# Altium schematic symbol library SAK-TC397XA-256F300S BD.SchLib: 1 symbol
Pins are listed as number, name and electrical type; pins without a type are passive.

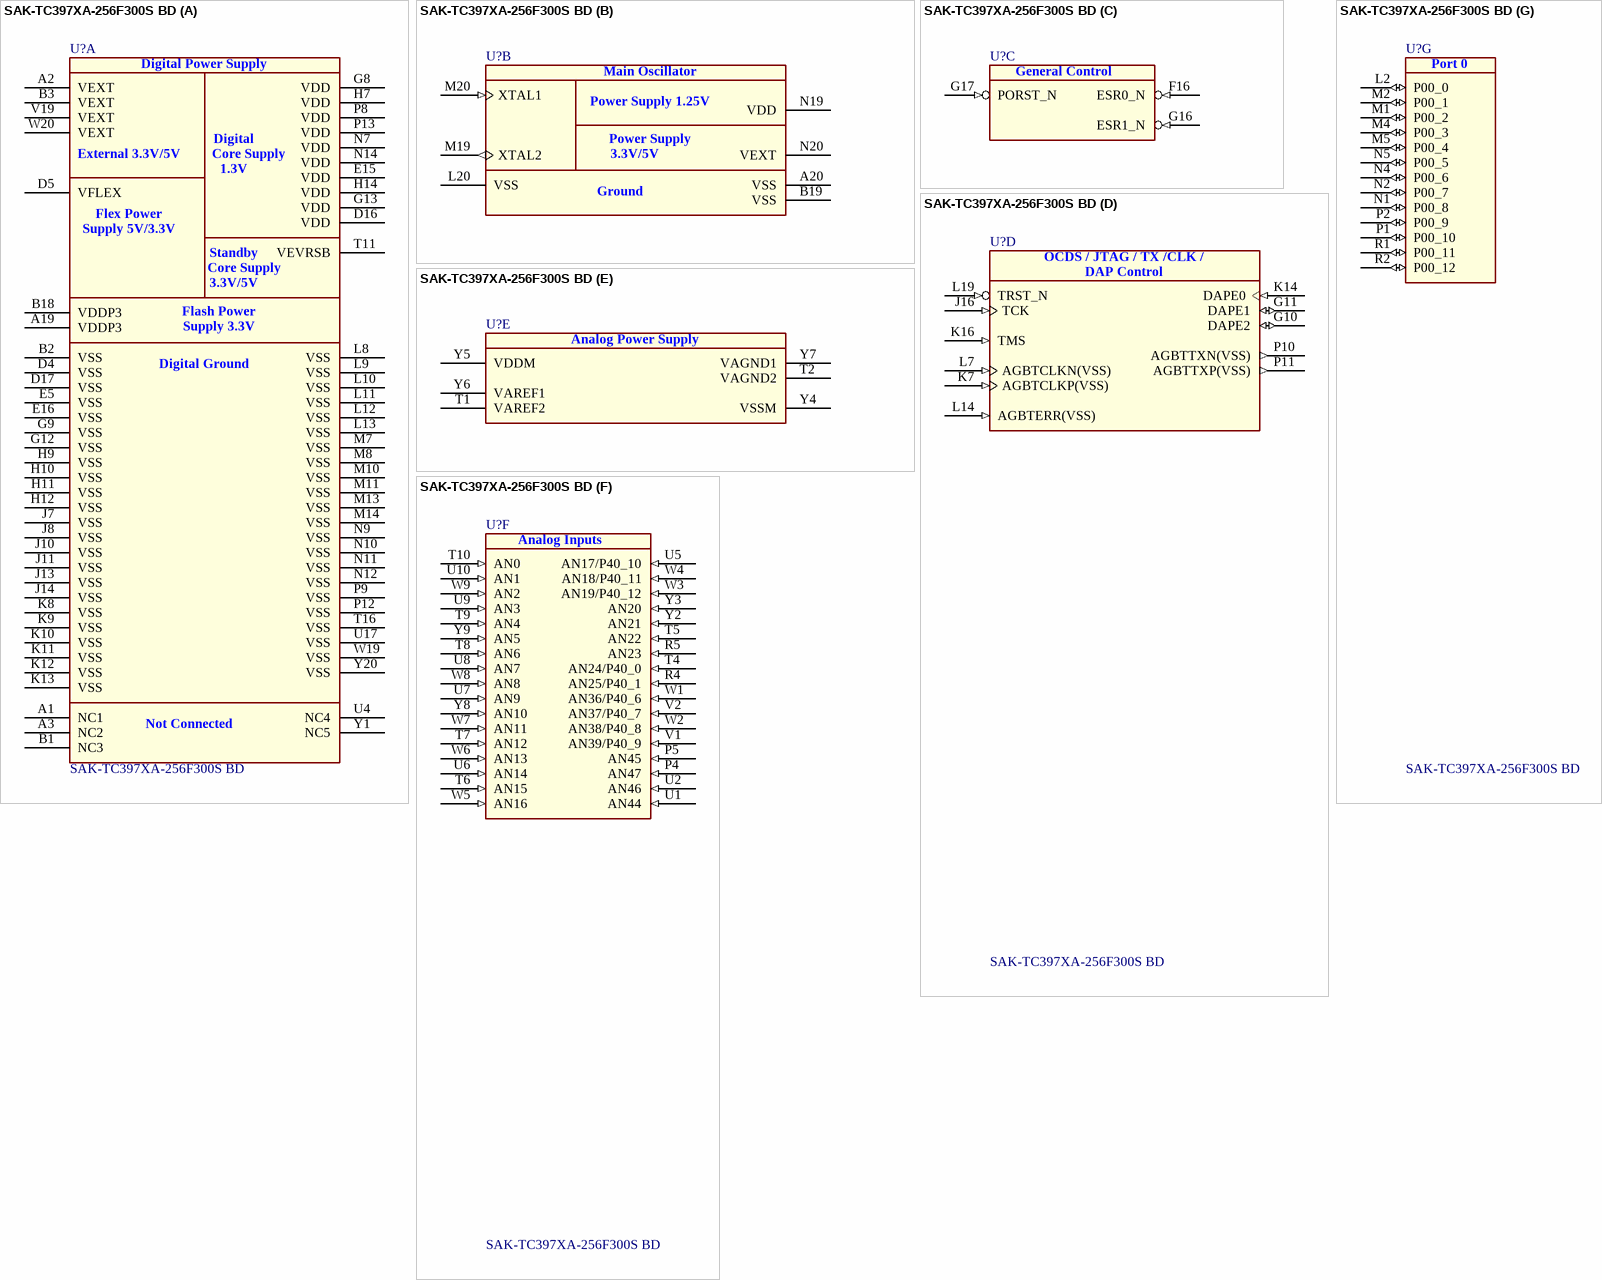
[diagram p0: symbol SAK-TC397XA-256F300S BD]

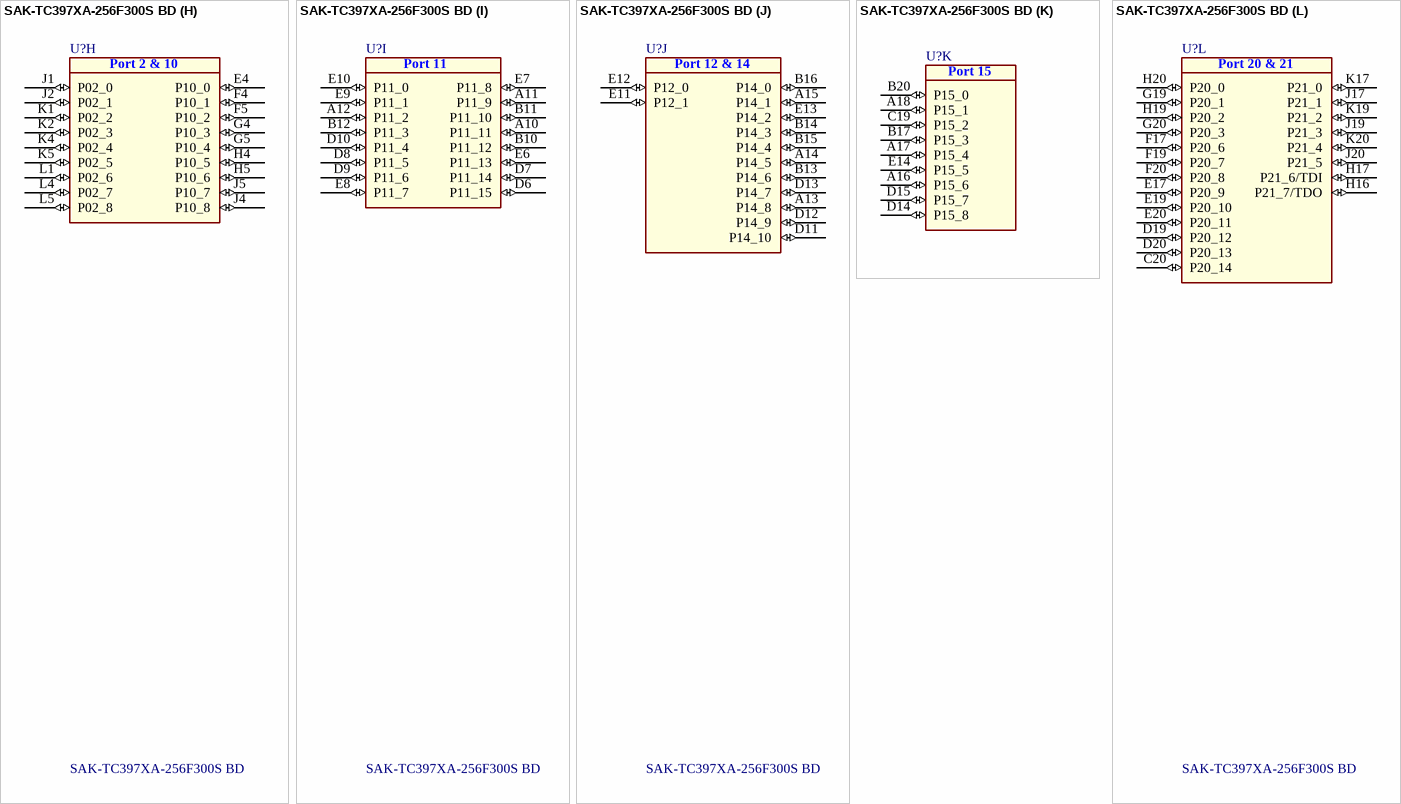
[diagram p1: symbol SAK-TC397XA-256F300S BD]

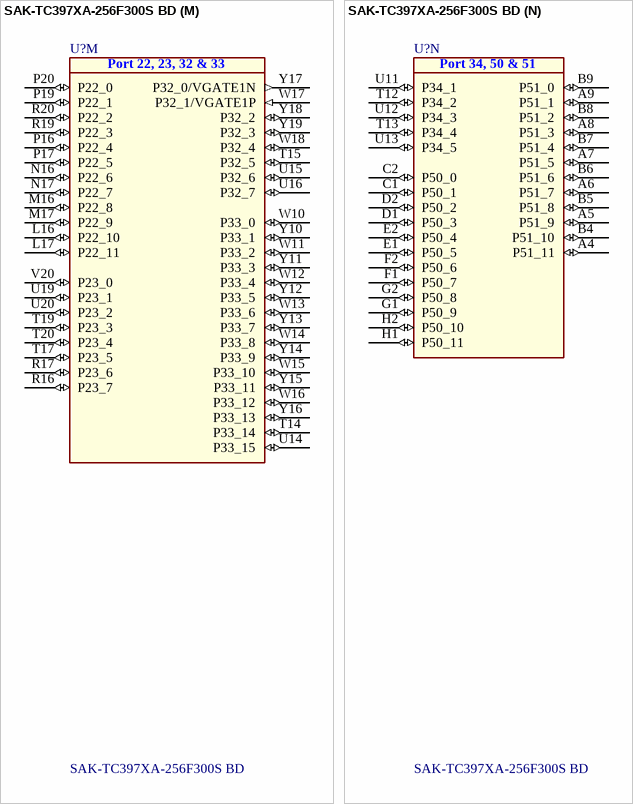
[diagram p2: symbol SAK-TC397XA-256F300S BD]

## SAK-TC397XA-256F300S BD
designator U?
AURIX TC39x, 32-Bit Single-Chip Microcontroller; Manufacturer: Infineon Technologies
footprint LF-BGA-292
part A pins: A1 NC1 "Not connected", A2 VEXT (power) "External Power Supply (5V / 3.3V)", A3 NC2 "Not connected", A19 VDDP3 (power) "Flash Power Supply (3.3V)", B1 NC3 "Not connected", B2 VSS (power) "Digital Ground", B3 VEXT (power) "External Power Supply (5V / 3.3V)", B18 VDDP3 (power) "Flash Power Supply (3.3V)", D4 VSS (power) "Digital Ground", D5 VFLEX (power) "Digital Power Supply for Flex Port Pads (5V / 3.3V)", D16 VDD (power) "Digital Core Power Supply (1.25V)", D17 VSS (power) "Digital Ground", E5 VSS (power) "Digital Ground", E15 VDD (power) "Digital Core Power Supply (1.25V)", E16 VSS (power) "Digital Ground", G8 VDD (power) "Digital Core Power Supply", G9 VSS (power) "Digital Ground", G12 VSS (power) "Digital Ground", G13 VDD (power) "Digital Core Power Supply (1.25V)", H7 VDD (power) "Digital Core Power Supply", H9 VSS (power) "Digital Ground", H10 VSS (power) "Digital Ground", H11 VSS (power) "Digital Ground", H12 VSS (power) "Digital Ground", H14 VDD (power) "Digital Core Power Supply (1.25V)", J7 VSS (power) "Digital Ground", J8 VSS (power) "Digital Ground", J10 VSS (power) "Digital Ground", J11 VSS (power) "Digital Ground", J13 VSS (power) "Digital Ground", J14 VSS (power) "Digital Ground", K8 VSS (power) "Digital Ground", K9 VSS (power) "Digital Ground", K10 VSS (power) "Digital Ground", K11 VSS (power) "Digital Ground", K12 VSS (power) "Digital Ground", K13 VSS (power) "Digital Ground", L8 VSS (power) "Digital Ground", L9 VSS (power) "Digital Ground", L10 VSS (power) "Digital Ground", L11 VSS (power) "Digital Ground", L12 VSS (power) "Digital Ground", L13 VSS (power) "Digital Ground", M7 VSS (power) "Digital Ground", M8 VSS (power) "Digital Ground", M10 VSS (power) "Digital Ground", M11 VSS (power) "Digital Ground", M13 VSS (power) "Digital Ground", M14 VSS (power) "Digital Ground", N7 VDD (power) "Digital Core Power Supply (1.25V)", N9 VSS (power) "Digital Ground", N10 VSS (power) "Digital Ground", N11 VSS (power) "Digital Ground", N12 VSS (power) "Digital Ground", N14 VDD (power) "Digital Core Power Supply (1.25V)", P8 VDD (power) "Digital Core Power Supply (1.25V)", P9 VSS (power) "Digital Ground", P12 VSS (power) "Digital Ground", P13 VDD (power) "Digital Core Power Supply (1.25V)", T11 VEVRSB (power) "Standby Power Supply (5V / 3.3V) for the Standby SRAM", T16 VSS (power) "Digital Ground", U4 NC4 "Not connected", U17 VSS (power) "Digital Ground", V19 VEXT (power) "External Power Supply (5V / 3.3V)", W19 VSS (power) "Digital Ground", W20 VEXT (power) "External Power Supply (5V / 3.3V)", Y1 NC5 "Not connected", Y20 VSS (power) "Digital Ground"
part B pins: A20 VSS (power) "Digital Ground", B19 VSS (power) "Digital Ground", L20 VSS (power) "Digital Ground", M19 XTAL2 (out) "XTAL2. Main Oscillator/PLL/Clock Generator OUTPUT", M20 XTAL1 (in) "XTAL1. Main Oscillator/PLL/Clock Generator Input", N19 VDD (power) "Digital Core Power Supply (1.25V)", N20 VEXT (power) "External Power Supply (5V / 3.3V)"
part C pins: F16 ESR0_N (in) "ESR0 Port Pin input - can be used to trigger a reset or an NMI", G16 ESR1_N (in) "ESR1 Port Pin input - can be used to trigger a reset or an NMI", G17 PORST_N (in) "PORST pin input"
part D pins: G10 DAPE2 (io) "DAPE: DAPE2 Data I/O", G11 DAPE1 (io) "DAPE: DAPE1 Data I/O", J16 TCK (in) "JTAG Module Clock Input", K7 AGBTCLKP(VSS) (in) "AGBT Input", K14 DAPE0 (in) "DAPE: DAPE0 Clock Input", K16 TMS (in) "JTAG Module State Machine Control Input", L7 AGBTCLKN(VSS) (in) "AGBT Input", L14 AGBTERR(VSS) (in) "AGBT Input", L19 TRST_N (in) "JTAG Module Reset/Enable Input", P10 AGBTTXN(VSS) (out) "AGBT Output", P11 AGBTTXP(VSS) (out) "AGBT Output"
part E pins: T1 VAREF2 (power) "Positive Analog Reference Voltage 2", T2 VAGND2 (power) "Negative Analog Reference Voltage 2", Y4 VSSM (power) "Analog Ground for VDDM", Y5 VDDM (power) "ADC Analog Power Supply (5V / 3.3V)", Y6 VAREF1 (power) "Positive Analog Reference Voltage 1", Y7 VAGND1 (power) "Negative Analog Reference Voltage 1"
part F pins: P4 AN47 (in) "Analog Input 47", P5 AN45 (in) "Analog Input 45", R4 AN25/P40_1 (in) "Analog Input 25", R5 AN23 (in) "Analog Input 23", T4 AN24/P40_0 (in) "Analog Input 24", T5 AN22 (in) "Analog Input 22", T6 AN15 (in) "Analog Input 15", T7 AN12 (in) "Analog Input 12", T8 AN6 (in) "Analog Input 6", T9 AN4 (in) "Analog Input 4", T10 AN0 (in) "Analog Input 0", U1 AN44 (in) "Analog Input 44", U2 AN46 (in) "Analog Input 46", U5 AN17/P40_10 (in) "Analog Input 17", U6 AN14 (in) "Analog Input 14", U7 AN9 (in) "Analog Input 9", U8 AN7 (in) "Analog Input 7", U9 AN3 (in) "Analog Input 3", U10 AN1 (in) "Analog Input 1", V1 AN39/P40_9 (in) "Analog Input 39", V2 AN37/P40_7 (in) "Analog Input 37", W1 AN36/P40_6 (in) "Analog Input 36", W2 AN38/P40_8 (in) "Analog Input 38", W3 AN19/P40_12 (in) "Analog Input 19", W4 AN18/P40_11 (in) "Analog Input 18", W5 AN16 (in) "Analog Input 16", W6 AN13 (in) "Analog Input 13", W7 AN11 (in) "Analog Input 11", W8 AN8 (in) "Analog Input 8", W9 AN2 (in) "Analog Input 2", Y2 AN21 (in) "Analog Input 21", Y3 AN20 (in) "Analog Input 20", Y8 AN10 (in) "Analog Input 10", Y9 AN5 (in) "Analog Input 5"
part G pins: L2 P00_0 (io) "General-purpose input/output", M1 P00_2 (io) "General-purpose input/output", M2 P00_1 (io) "General-purpose input/output", M4 P00_3 (io) "General-purpose input/output", M5 P00_4 (io) "General-purpose input/output", N1 P00_8 (io) "General-purpose input/output", N2 P00_7 (io) "General-purpose input/output", N4 P00_6 (io) "General-purpose input/output", N5 P00_5 (io) "General-purpose input/output", P1 P00_10 (io) "General-purpose input/output", P2 P00_9 (io) "General-purpose input/output", R1 P00_11 (io) "General-purpose input/output", R2 P00_12 (io) "General-purpose input/output"
part H pins: E4 P10_0 (io) "General-purpose input/output", F4 P10_1 (io) "General-purpose input/output", F5 P10_2 (io) "General-purpose input/output", G4 P10_3 (io) "General-purpose input/output", G5 P10_4 (io) "General-purpose input/output", H4 P10_5 (io) "General-purpose input/output", H5 P10_6 (io) "General-purpose input/output", J1 P02_0 (io) "General-purpose input/output", J2 P02_1 (io) "General-purpose input/output", J4 P10_8 (io) "General-purpose input/output", J5 P10_7 (io) "General-purpose input/output", K1 P02_2 (io) "General-purpose input/output", K2 P02_3 (io) "General-purpose input/output", K4 P02_4 (io) "General-purpose input/output", K5 P02_5 (io) "General-purpose input/output", L1 P02_6 (io) "General-purpose input/output", L4 P02_7 (io) "General-purpose input/output", L5 P02_8 (io) "General-purpose input/output"
part I pins: A10 P11_11 (io) "General-purpose input/output", A11 P11_9 (io) "General-purpose input/output", A12 P11_2 (io) "General-purpose input/output", B10 P11_12 (io) "General-purpose input/output", B11 P11_10 (io) "General-purpose input/output", B12 P11_3 (io) "General-purpose input/output", D6 P11_15 (io) "General-purpose input/output", D7 P11_14 (io) "General-purpose input/output", D8 P11_5 (io) "General-purpose input/output", D9 P11_6 (io) "General-purpose input/output", D10 P11_4 (io) "General-purpose input/output", E6 P11_13 (io) "General-purpose input/output", E7 P11_8 (io) "General-purpose input/output", E8 P11_7 (io) "General-purpose input/output", E9 P11_1 (io) "General-purpose input/output", E10 P11_0 (io) "General-purpose input/output"
part J pins: A13 P14_8 (io) "General-purpose input/output", A14 P14_5 (io) "General-purpose input/output", A15 P14_1 (io) "General-purpose input/output", B13 P14_6 (io) "General-purpose input/output", B14 P14_3 (io) "General-purpose input/output", B15 P14_4 (io) "General-purpose input/output", B16 P14_0 (io) "General-purpose input/output", D11 P14_10 (io) "General-purpose input/output", D12 P14_9 (io) "General-purpose input/output", D13 P14_7 (io) "General-purpose input/output", E11 P12_1 (io) "General-purpose input/output", E12 P12_0 (io) "General-purpose input/output", E13 P14_2 (io) "General-purpose input/output"
part K pins: A16 P15_6 (io) "General-purpose input/output", A17 P15_4 (io) "General-purpose input/output", A18 P15_1 (io) "General-purpose input/output", B17 P15_3 (io) "General-purpose input/output", B20 P15_0 (io) "General-purpose input/output", C19 P15_2 (io) "General-purpose input/output", D14 P15_8 (io) "General-purpose input/output", D15 P15_7 (io) "General-purpose input/output", E14 P15_5 (io) "General-purpose input/output"
part L pins: C20 P20_14 (io) "General-purpose input/output", D19 P20_12 (io) "General-purpose input/output", D20 P20_13 (io) "General-purpose input/output", E17 P20_9 (io) "General-purpose input/output", E19 P20_10 (io) "General-purpose input/output", E20 P20_11 (io) "General-purpose input/output", F17 P20_6 (io) "General-purpose input/output", F19 P20_7 (io) "General-purpose input/output", F20 P20_8 (io) "General-purpose input/output", G19 P20_1 (io) "General-purpose input/output", G20 P20_3 (io) "General-purpose input/output", H16 P21_7/TDO (io) "General-purpose input/output", H17 P21_6/TDI (io) "General-purpose input/output", H19 P20_2 (io) "General-purpose input/output", H20 P20_0 (io) "General-purpose input/output", J17 P21_1 (io) "General-purpose input/output", J19 P21_3 (io) "General-purpose input/output", J20 P21_5 (io) "General-purpose input/output", K17 P21_0 (io) "General-purpose input/output", K19 P21_2 (io) "General-purpose input/output", K20 P21_4 (io) "General-purpose input/output"
part M pins: L16 P22_10 (io) "General-purpose input/output", L17 P22_11 (io) "General-purpose input/output", M16 P22_8 (io) "General-purpose input/output", M17 P22_9 (io) "General-purpose input/output", N16 P22_6 (io) "General-purpose input/output", N17 P22_7 (io) "General-purpose input/output", P16 P22_4 (io) "General-purpose input/output", P17 P22_5 (io) "General-purpose input/output", P19 P22_1 (io) "General-purpose input/output", P20 P22_0 (io) "General-purpose input/output", R16 P23_7 (io) "General-purpose input/output", R17 P23_6 (io) "General-purpose input/output", R19 P22_3 (io) "General-purpose input/output", R20 P22_2 (io) "General-purpose input/output", T14 P33_14 (io) "General-purpose input/output", T15 P32_5 (io) "General-purpose input/output", T17 P23_5 (io) "General-purpose input/output", T19 P23_3 (io) "General-purpose input/output", T20 P23_4 (io) "General-purpose input/output", U14 P33_15 (io) "General-purpose input/output", U15 P32_6 (io) "General-purpose input/output", U16 P32_7 (io) "General-purpose input/output", U19 P23_1 (io) "General-purpose input/output", U20 P23_2 (io) "General-purpose input/output", V20 P23_0 (io) "General-purpose input/output", W10 P33_0 (io) "General-purpose input/output", W11 P33_2 (io) "General-purpose input/output", W12 P33_4 (io) "General-purpose input/output", W13 P33_6 (io) "General-purpose input/output", W14 P33_8 (io) "General-purpose input/output", W15 P33_10 (io) "General-purpose input/output", W16 P33_12 (io) "General-purpose input/output", W17 P32_1/VGATE1P (in) "General-purpose input/output", W18 P32_4 (io) "General-purpose input/output", Y10 P33_1 (io) "General-purpose input/output", Y11 P33_3 (io) "General-purpose input/output", Y12 P33_5 (io) "General-purpose input/output", Y13 P33_7 (io) "General-purpose input/output", Y14 P33_9 (io) "General-purpose input/output", Y15 P33_11 (io) "General-purpose input/output", Y16 P33_13 (io) "General-purpose input/output", Y17 P32_0/VGATE1N (out) "DCDC N ch. MOSFET gate driver output", Y18 P32_2 (io) "General-purpose input/output", Y19 P32_3 (io) "General-purpose input/output"
part N pins: A4 P51_11 (io) "General-purpose input/output", A5 P51_9 (io) "General-purpose input/output", A6 P51_7 (io) "General-purpose input/output", A7 P51_5 (io) "General-purpose input/output", A8 P51_3 (io) "General-purpose input/output", A9 P51_1 (io) "General-purpose input/output", B4 P51_10 (io) "General-purpose input/output", B5 P51_8 (io) "General-purpose input/output", B6 P51_6 (io) "General-purpose input/output", B7 P51_4 (io) "General-purpose input/output", B8 P51_2 (io) "General-purpose input/output", B9 P51_0 (io) "General-purpose input/output", C1 P50_1 (io) "General-purpose input/output", C2 P50_0 (io) "General-purpose input/output", D1 P50_3 (io) "General-purpose input/output", D2 P50_2 (io) "General-purpose input/output", E1 P50_5 (io) "General-purpose input/output", E2 P50_4 (io) "General-purpose input/output", F1 P50_7 (io) "General-purpose input/output", F2 P50_6 (io) "General-purpose input/output", G1 P50_9 (io) "General-purpose input/output", G2 P50_8 (io) "General-purpose input/output", H1 P50_11 (io) "General-purpose input/output", H2 P50_10 (io) "General-purpose input/output", T12 P34_2 (io) "General-purpose input/output", T13 P34_4 (io) "General-purpose input/output", U11 P34_1 (io) "General-purpose input/output", U12 P34_3 (io) "General-purpose input/output", U13 P34_5 (io) "General-purpose input/output"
